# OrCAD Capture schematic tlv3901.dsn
size A
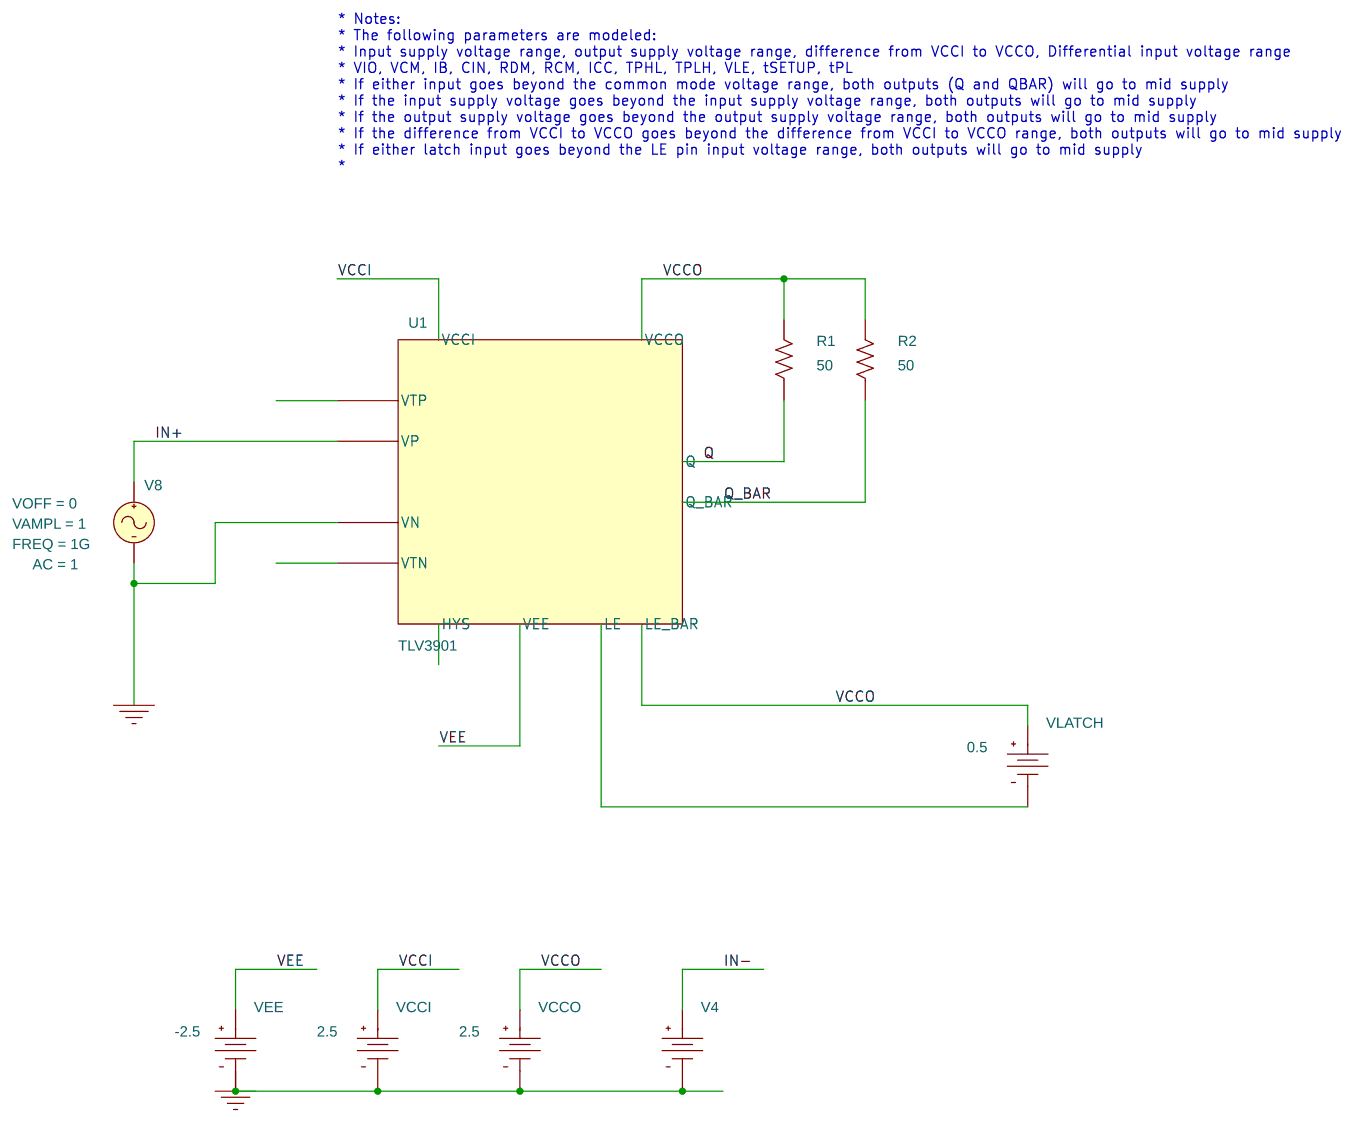
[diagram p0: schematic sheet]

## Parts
R1  50  [AXRC05]
R2  50  [AXRC05]
U1  TLV3901
V4  VDC
V8  VSIN
VCCI  VDC
VCCO  VDC
VEE  VDC
VLATCH  VDC

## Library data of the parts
R1 R2 = R
U1 = TLV3901
V4 = VDC
V8 = VSIN: AC: 1; FREQ: 1G; VAMPL: 1; VOFF: 0
VCCI VCCO = VDC: DC: 2.5
VEE = VDC: DC: -2.5
VLATCH = VDC: DC: 0.5

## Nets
VCCI: U1.VCCI VCCI.0(+)
VCCO: R1.2 R2.2 U1.LE_BAR U1.VCCO VCCO.0(+) VLATCH.0(+)
VEE: U1.VEE VEE.0(+)
0: U1.VN V4.1(-) V8.2(-) VCCI.1(-) VCCO.1(-) VEE.1(-)
IN+: U1.VP V8.1(+)
IN-: V4.0(+)
Q: R1.1 U1.Q
Q_BAR: R2.1 U1.Q_BAR
N10821: U1.LE VLATCH.1(-)

Not connected (* = marked no-connect by the designer): U1 HYS VTN VTP

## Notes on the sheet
- * Notes:
  * The following parameters are modeled:
  * Input supply voltage range, output supply voltage range, difference from VCCI to VCCO, Differential input voltage range
  * VIO, VCM, IB, CIN, RDM, RCM, ICC, TPHL, TPLH, VLE, tSETUP, tPL
  * If either input goes beyond the common mode voltage range, both outputs (Q and QBAR) will go to mid supply
  * If the input supply voltage goes beyond the input supply voltage range, both outputs will go to mid supply
  * If the output supply voltage goes beyond the output supply voltage range, both outputs will go to mid supply
  * If the difference from VCCI to VCCO goes beyond the difference from VCCI to VCCO range, both outputs will go to mid supply
  * If either latch input goes beyond the LE pin input voltage range, both outputs will go to mid supply
  *
